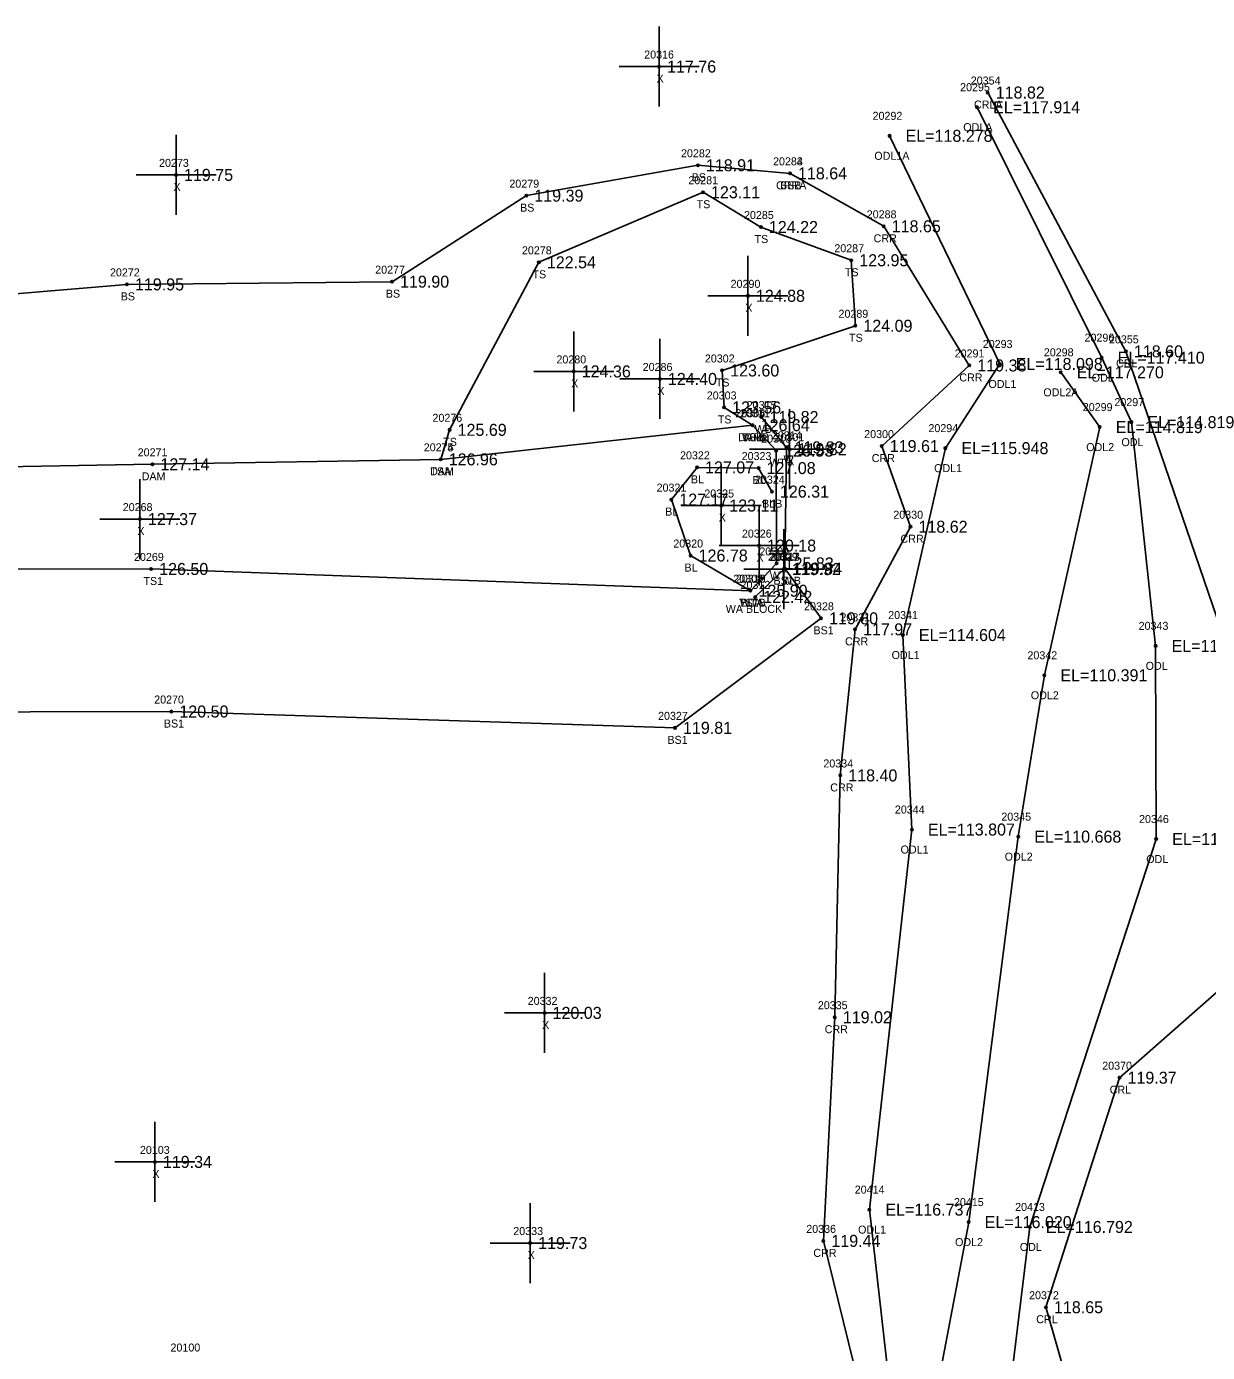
# Model space of a CAD drawing. Extents: x 2375812 to 2377225, y 1024470 to 1025135.
# Drawn here: x 2376402.6 to 2376550.1, y 1024966.8 to 1025132.5 of the extents above; entities that cross this region are included whole.
import ezdxf

# ---------------------------------------------------------------- set-up
doc = ezdxf.new("R2010")
doc.units = 0
for name, color, linetype in [('RD_DTM_BkLn1', 7, 'Continuous'), ('RD_DTM_BkLn2', 7, 'Continuous'), ('RD_DTM_BkLn_txCode', 7, 'Continuous'), ('RD_EX_BldgApp', 7, 'Continuous'), ('RD_EX_Dam', 7, 'Continuous'), ('RD_EX_Dam_txCode', 7, 'Continuous'), ('RD_EX_H2O', 7, 'Continuous'), ('RD_EX_H2O_txCode', 7, 'Continuous'), ('RD_EX_Misc', 7, 'Continuous'), ('RD_EX_Misc_txCode', 7, 'Continuous'), ('RD_EX_TX_Dam_ELEV', 7, 'Continuous'), ('RD_EX_TX_H2O_ELEV', 7, 'Continuous'), ('RD_EX_TX_Misc_ELEV', 7, 'Continuous'), ('RD_SMD_Locator', 7, 'Continuous')]:
    doc.layers.add(name, color=color, linetype=linetype)

msp = doc.modelspace()

# ---------------------------------------------------------------- linework, layer by layer
at = {"layer": 'RD_DTM_BkLn1'}
msp.add_lwpolyline([(2376493.03, 1025062.01), (2376485.55, 1025066.41), (2376483.14, 1025073.4), (2376486.35, 1025077.43), (2376494.04, 1025077.34), (2376495.71, 1025074.4)], dxfattribs=at)
at = {"layer": 'RD_DTM_BkLn2'}
for points in [[(2375847.51, 1025092.15), (2375876.46, 1025088.72), (2375981.63, 1025092.39), (2376090.5, 1025090.54), (2376205.11, 1025096.35), (2376313.64, 1025091.79), (2376415.11, 1025100.3), (2376448.24, 1025100.64), (2376465.02, 1025111.39), (2376486.46, 1025115.19), (2376497.97, 1025114.18)], [(2376454.32, 1025078.43), (2376455.43, 1025082.12), (2376466.58, 1025103.06), (2376487.1, 1025111.82), (2376494.33, 1025107.47), (2376505.63, 1025103.32), (2376506.14, 1025095.13), (2376489.49, 1025089.54), (2376489.73, 1025084.92), (2376493.3, 1025082.7)], [(2375847.93, 1025050.33), (2375875.91, 1025056.72), (2375981.44, 1025060.56), (2376091.98, 1025062.38), (2376205.71, 1025062.75), (2376313.72, 1025064.62), (2376418.13, 1025064.73), (2376493.03, 1025062.01)], [(2375848.17, 1025037.34), (2375876.1, 1025042.73), (2375981.89, 1025042.57), (2376092.59, 1025040.39), (2376206.51, 1025041.77), (2376314.64, 1025046.65), (2376420.66, 1025046.91), (2376483.6, 1025044.87), (2376501.85, 1025058.56), (2376497.33, 1025064.77)]]:
    msp.add_lwpolyline(points, dxfattribs=at)
at = {"layer": 'RD_EX_BldgApp'}
for points in [[(2376493.03, 1025062.01), (2376496.3, 1025065.42), (2376496.24, 1025079.52), (2376493.3, 1025082.7)], [(2376493.62, 1025061.24), (2376497.33, 1025064.77), (2376497.53, 1025079.93), (2376494.4, 1025083.72)]]:
    msp.add_lwpolyline(points, dxfattribs=at)
at = {"layer": 'RD_EX_Dam'}
msp.add_lwpolyline([(2375847.73, 1025068.2), (2375876.5, 1025071.72), (2375981.19, 1025074.08), (2376091.91, 1025074.48), (2376205.24, 1025076.35), (2376314.21, 1025075.97), (2376418.29, 1025077.81), (2376454.32, 1025078.43), (2376493.3, 1025082.7)], dxfattribs=at)
at = {"layer": 'RD_EX_H2O'}
for points in [[(2376522.68, 1025124.28), (2376539.95, 1025091.93), (2376552.99, 1025053.79), (2376555.76, 1025047.24), (2376554.71, 1025040.88), (2376557.55, 1025026.68), (2376555.84, 1025015.85), (2376539.15, 1025001.14), (2376529.96, 1024972.45), (2376538.09, 1024944), (2376543.21, 1024910.85), (2376536.76, 1024892.22), (2376537.46, 1024874.15), (2376528.94, 1024859.35), (2376567.86, 1024843.78), (2376572.98, 1024831.38), (2376577.78, 1024803.44), (2376559.73, 1024782.76)], [(2376521.35, 1025122.45), (2376536.92, 1025091.14), (2376540.63, 1025083.08), (2376543.66, 1025055.12), (2376543.73, 1025030.97), (2376527.94, 1024982.48), (2376525.52, 1024962.71), (2376529, 1024940.86), (2376531.15, 1024912.48), (2376521.82, 1024868), (2376529.09, 1024848.8), (2376562.19, 1024842.5), (2376569.47, 1024830.15), (2376574.05, 1024803.85), (2376558.51, 1024784.52), (2376559.64, 1024766), (2376613.77, 1024719.65), (2376596.93, 1024694.68), (2376526.36, 1024664.12), (2376525.63, 1024655.55), (2376574.03, 1024595.3), (2376579.09, 1024545.56), (2376560.1, 1024512.81), (2376580.22, 1024476.29)], [(2376510.41, 1025118.87), (2376524.18, 1025090.35), (2376517.39, 1025079.83), (2376512.07, 1025056.47), (2376513.2, 1025032.16), (2376507.89, 1024984.65), (2376510.96, 1024957.77), (2376506.15, 1024940.79), (2376503.27, 1024912.21), (2376508.8, 1024872.61), (2376520.24, 1024833.34), (2376559.55, 1024828.46), (2376560.55, 1024802.93), (2376553.87, 1024788.72), (2376548.34, 1024764.64), (2376601.21, 1024719.97), (2376590.62, 1024704.71), (2376516.74, 1024677.65), (2376510.14, 1024650.4), (2376567.6, 1024571.64), (2376569.87, 1024553.24), (2376548.12, 1024513.5), (2376565.22, 1024475.98)], [(2376497.97, 1025114.18), (2376509.68, 1025107.56), (2376520.38, 1025090.17), (2376509.44, 1025080.09), (2376513.03, 1025070.01), (2376506.1, 1025057.18), (2376504.25, 1025038.92), (2376503.57, 1025008.7), (2376502.14, 1024980.74), (2376507.14, 1024960.43), (2376497.53, 1024949.18), (2376497, 1024946.35), (2376491.09, 1024911.59), (2376491.85, 1024896.06), (2376492.09, 1024868.56), (2376505.72, 1024835.56), (2376529.83, 1024824.06), (2376555.53, 1024827.27), (2376554.79, 1024808.22), (2376551.26, 1024790.28)], [(2376531.81, 1025089.31), (2376536.68, 1025082.46), (2376529.76, 1025051.44), (2376526.5, 1025031.27), (2376520.3, 1024983.09), (2376515.68, 1024958.74), (2376517.02, 1024940.85), (2376517.68, 1024912.41), (2376515.57, 1024873.2), (2376528.33, 1024834.7)]]:
    msp.add_lwpolyline(points, dxfattribs=at)
at = {"layer": 'RD_EX_Misc'}
for p, q in [((2376481.61, 1025122.53), (2376481.61, 1025132.53)), ((2376476.61, 1025127.53), (2376486.61, 1025127.53)), ((2376421.24, 1025108.99), (2376421.24, 1025118.99)), ((2376416.24, 1025113.99), (2376426.24, 1025113.99)), ((2376492.71, 1025093.87), (2376492.71, 1025103.87)), ((2376487.71, 1025098.87), (2376497.71, 1025098.87)), ((2376470.94, 1025084.42), (2376470.94, 1025094.42)), ((2376481.71, 1025083.48), (2376481.71, 1025093.48)), ((2376465.94, 1025089.42), (2376475.94, 1025089.42)), ((2376476.71, 1025088.48), (2376486.71, 1025088.48)), ((2376497.92, 1025074.7), (2376497.92, 1025084.7)), ((2376492.92, 1025079.7), (2376502.92, 1025079.7)), ((2376489.38, 1025067.66), (2376489.38, 1025077.66)), ((2376416.73, 1025065.96), (2376416.73, 1025075.96)), ((2376484.38, 1025072.66), (2376494.38, 1025072.66)), ((2376494.1, 1025062.65), (2376494.1, 1025072.65)), ((2376411.73, 1025070.96), (2376421.73, 1025070.96)), ((2376497.2, 1025059.71), (2376497.2, 1025069.71)), ((2376489.1, 1025067.65), (2376499.1, 1025067.65)), ((2376492.2, 1025064.71), (2376502.2, 1025064.71)), ((2376467.3, 1025004.24), (2376467.3, 1025014.24)), ((2376462.3, 1025009.24), (2376472.3, 1025009.24)), ((2376418.6, 1024985.61), (2376418.6, 1024995.61)), ((2376413.6, 1024990.61), (2376423.6, 1024990.61)), ((2376465.5, 1024975.47), (2376465.5, 1024985.47)), ((2376460.5, 1024980.47), (2376470.5, 1024980.47))]:
    msp.add_line(p, q, dxfattribs=at)
at = {"layer": 'RD_SMD_Locator'}
for centre in [(2376481.61, 1025127.53), (2376522.68, 1025124.28), (2376521.35, 1025122.45), (2376510.41, 1025118.87), (2376421.24, 1025113.99), (2376486.46, 1025115.19), (2376497.97, 1025114.18), (2376497.97, 1025114.18), (2376465.02, 1025111.39), (2376487.1, 1025111.82), (2376494.33, 1025107.47), (2376509.68, 1025107.56), (2376466.58, 1025103.06), (2376505.63, 1025103.32), (2376448.24, 1025100.64), (2376415.11, 1025100.3), (2376492.71, 1025098.87), (2376506.14, 1025095.13), (2376536.92, 1025091.14), (2376539.95, 1025091.93), (2376470.94, 1025089.42), (2376489.49, 1025089.54), (2376520.38, 1025090.17), (2376524.18, 1025090.35), (2376531.81, 1025089.31), (2376481.71, 1025088.48), (2376489.73, 1025084.92), (2376493.3, 1025082.7), (2376493.3, 1025082.7), (2376493.3, 1025082.7), (2376494.4, 1025083.72), (2376536.68, 1025082.46), (2376540.63, 1025083.08), (2376455.43, 1025082.12), (2376496.24, 1025079.52), (2376497.53, 1025079.93), (2376497.92, 1025079.7), (2376509.44, 1025080.09), (2376517.39, 1025079.83), (2376418.29, 1025077.81), (2376454.32, 1025078.43), (2376454.32, 1025078.43), (2376486.35, 1025077.43), (2376494.04, 1025077.34), (2376495.71, 1025074.4), (2376483.14, 1025073.4), (2376489.38, 1025072.66), (2376416.73, 1025070.96), (2376513.03, 1025070.01), (2376494.1, 1025067.65), (2376485.55, 1025066.41), (2376418.13, 1025064.73), (2376496.3, 1025065.42), (2376497.2, 1025064.71), (2376497.33, 1025064.77), (2376497.33, 1025064.77), (2376493.03, 1025062.01), (2376493.03, 1025062.01), (2376493.03, 1025062.01), (2376493.62, 1025061.24), (2376501.85, 1025058.56), (2376506.1, 1025057.18), (2376512.07, 1025056.47), (2376543.66, 1025055.12), (2376529.76, 1025051.44), (2376420.66, 1025046.91), (2376483.6, 1025044.87), (2376504.25, 1025038.92), (2376513.2, 1025032.16), (2376526.5, 1025031.27), (2376543.73, 1025030.97), (2376467.3, 1025009.24), (2376503.57, 1025008.7), (2376539.15, 1025001.14), (2376418.6, 1024990.61), (2376507.89, 1024984.65), (2376520.3, 1024983.09), (2376527.94, 1024982.48), (2376465.5, 1024980.47), (2376502.14, 1024980.74), (2376529.96, 1024972.45)]:
    msp.add_circle(centre, 0.15, dxfattribs=at)

# ---------------------------------------------------------------- texts
at = {"layer": 'RD_DTM_BkLn_txCode'}
for s, p in [('20282', (2376484.35, 1025116.19)), ('20283', (2376495.85, 1025115.18)), ('BS', (2376485.68, 1025113.19)), ('20279', (2376462.9, 1025112.39)), ('20281', (2376485.26, 1025112.82)), ('BSB', (2376496.72, 1025112.18)), ('TS', (2376486.3, 1025109.82)), ('BS', (2376464.24, 1025109.39)), ('20285', (2376492.22, 1025108.47)), ('TS', (2376493.54, 1025105.47)), ('20278', (2376464.47, 1025104.06)), ('20287', (2376503.51, 1025104.32)), ('20277', (2376446.13, 1025101.64)), ('20272', (2376412.99, 1025101.3)), ('TS', (2376465.79, 1025101.06)), ('TS', (2376504.83, 1025101.32)), ('BS', (2376414.33, 1025098.3)), ('BS', (2376447.46, 1025098.64)), ('20289', (2376504.03, 1025096.13)), ('TS', (2376505.35, 1025093.13)), ('20302', (2376487.33, 1025090.54)), ('TS', (2376488.69, 1025087.54)), ('20303', (2376487.57, 1025085.92)), ('20305', (2376491.14, 1025083.7)), ('20276', (2376453.29, 1025083.12)), ('TS', (2376488.94, 1025082.92)), ('TS', (2376454.63, 1025080.12)), ('TSB', (2376492.03, 1025080.7)), ('20275', (2376452.2, 1025079.43)), ('20322', (2376484.23, 1025078.43)), ('20323', (2376491.93, 1025078.34)), ('TSA', (2376453.03, 1025076.43)), ('BL', (2376485.59, 1025075.43)), ('BL', (2376493.29, 1025075.34)), ('20324', (2376493.59, 1025075.4)), ('20321', (2376481.3, 1025074.4)), ('BLB', (2376494.48, 1025072.4)), ('BL', (2376482.38, 1025071.4)), ('20320', (2376483.39, 1025067.41)), ('20269', (2376415.99, 1025065.73)), ('20329', (2376495.21, 1025065.77)), ('BL', (2376484.79, 1025064.41)), ('TS1', (2376417.17, 1025062.73)), ('20318', (2376491.2, 1025063.01)), ('20319', (2376491.2, 1025063.01)), ('BS1B', (2376495.91, 1025062.77)), ('TS1B', (2376491.6, 1025060.01)), ('BLA', (2376491.79, 1025060.01)), ('20328', (2376499.73, 1025059.56)), ('BS1', (2376500.9, 1025056.56)), ('20270', (2376418.51, 1025047.91)), ('20327', (2376481.48, 1025045.87)), ('BS1', (2376419.72, 1025044.91)), ('BS1', (2376482.65, 1025042.87))]:
    msp.add_text(s, height=1, dxfattribs=at).set_placement(p)
at = {"layer": 'RD_EX_Dam_txCode'}
for s, p in [('20304', (2376491.14, 1025083.7)), ('DAMB', (2376491.49, 1025080.7)), ('20271', (2376416.45, 1025078.81)), ('20274', (2376452.2, 1025079.43)), ('DAM', (2376416.95, 1025075.81)), ('DAM', (2376452.99, 1025076.43))]:
    msp.add_text(s, height=1, dxfattribs=at).set_placement(p)
at = {"layer": 'RD_EX_H2O_txCode'}
for s, p in [('20354', (2376520.56, 1025125.28)), ('20295', (2376519.23, 1025124.45)), ('CRLA', (2376520.96, 1025122.28)), ('20292', (2376508.29, 1025120.87)), ('ODLA', (2376519.62, 1025119.45)), ('20284', (2376495.85, 1025115.18)), ('ODL1A', (2376508.51, 1025115.87)), ('CRRA', (2376496.23, 1025112.18)), ('20288', (2376507.56, 1025108.56)), ('CRR', (2376508.42, 1025105.56)), ('20296', (2376534.78, 1025093.14)), ('20293', (2376522.06, 1025092.35)), ('20355', (2376537.83, 1025092.93)), ('20291', (2376518.55, 1025091.17)), ('20298', (2376529.69, 1025091.31)), ('CRL', (2376538.72, 1025089.93)), ('CRR', (2376519.13, 1025088.17)), ('ODL', (2376535.68, 1025088.14)), ('ODL1', (2376522.77, 1025087.35)), ('ODL2A', (2376529.63, 1025086.31)), ('20297', (2376538.51, 1025085.08)), ('20299', (2376534.56, 1025084.46)), ('20294', (2376515.27, 1025081.83)), ('20300', (2376507.24, 1025081.09)), ('ODL', (2376539.39, 1025080.08)), ('ODL2', (2376534.99, 1025079.46)), ('CRR', (2376508.18, 1025078.09)), ('ODL1', (2376515.98, 1025076.83)), ('20330', (2376510.88, 1025071.01)), ('CRR', (2376511.78, 1025068.01)), ('20341', (2376510.24, 1025058.47)), ('20331', (2376504.27, 1025058.18)), ('20343', (2376541.54, 1025057.12)), ('CRR', (2376504.85, 1025055.18)), ('ODL1', (2376510.67, 1025053.47)), ('20342', (2376527.64, 1025053.44)), ('ODL', (2376542.42, 1025052.12)), ('ODL2', (2376528.07, 1025048.44)), ('20334', (2376502.14, 1025039.92)), ('CRR', (2376503, 1025036.92)), ('20344', (2376511.08, 1025034.16)), ('20345', (2376524.38, 1025033.27)), ('20346', (2376541.59, 1025032.97)), ('ODL1', (2376511.79, 1025029.16)), ('ODL2', (2376524.8, 1025028.27)), ('ODL', (2376542.49, 1025027.97)), ('20335', (2376501.45, 1025009.7)), ('CRR', (2376502.31, 1025006.7)), ('20370', (2376536.99, 1025002.14)), ('CRL', (2376537.92, 1024999.14)), ('20414', (2376506.06, 1024986.65)), ('20415', (2376518.46, 1024985.09)), ('20413', (2376526.1, 1024984.48)), ('20336', (2376500, 1024981.74)), ('ODL1', (2376506.48, 1024981.65)), ('ODL2', (2376518.6, 1024980.09)), ('ODL', (2376526.69, 1024979.48)), ('CRR', (2376500.89, 1024978.74)), ('20372', (2376527.85, 1024973.45)), ('CRL', (2376528.74, 1024970.45)), ('20100', (2376420.55, 1024966.91))]:
    msp.add_text(s, height=1, dxfattribs=at).set_placement(p)
at = {"layer": 'RD_EX_Misc_txCode'}
for s, p in [('20316', (2376479.75, 1025128.53)), ('X', (2376481.3, 1025125.53)), ('20273', (2376419.12, 1025114.99)), ('X', (2376420.93, 1025111.99)), ('20290', (2376490.55, 1025099.87)), ('X', (2376492.39, 1025096.87)), ('20280', (2376468.78, 1025090.42)), ('20286', (2376479.56, 1025089.48)), ('X', (2376470.62, 1025087.42)), ('X', (2376481.39, 1025086.48)), ('20311', (2376491.74, 1025083.7)), ('20315', (2376492.56, 1025084.72)), ('WB', (2376493.55, 1025081.72)), ('WTB', (2376491.96, 1025080.7)), ('20310', (2376494.37, 1025080.52)), ('20314', (2376495.7, 1025080.93)), ('20301', (2376496.04, 1025080.7)), ('WT', (2376495.38, 1025077.52)), ('W', (2376497.16, 1025077.93)), ('X', (2376497.6, 1025077.7)), ('20325', (2376487.26, 1025073.66)), ('20268', (2376414.58, 1025071.96)), ('X', (2376489.07, 1025070.66)), ('X', (2376416.41, 1025068.96)), ('20326', (2376491.96, 1025068.65)), ('X', (2376493.79, 1025065.65)), ('20309', (2376494.14, 1025066.42)), ('20317', (2376495.37, 1025065.71)), ('20313', (2376495.49, 1025065.77)), ('WT', (2376495.44, 1025063.42)), ('20308', (2376490.88, 1025063.01)), ('20312', (2376491.79, 1025062.24)), ('X', (2376496.89, 1025062.71)), ('W', (2376496.96, 1025062.77)), ('WTA', (2376491.69, 1025060.01)), ('WA BLOCK', (2376489.94, 1025059.24)), ('20332', (2376465.19, 1025010.24)), ('X', (2376466.99, 1025007.24)), ('20103', (2376416.73, 1024991.61)), ('X', (2376418.29, 1024988.61)), ('20333', (2376463.39, 1024981.47)), ('X', (2376465.19, 1024978.47))]:
    msp.add_text(s, height=1, dxfattribs=at).set_placement(p)
at = {"layer": 'RD_EX_TX_Dam_ELEV'}
for s, p in [('126.64', (2376494.3, 1025081.95)), ('127.14', (2376419.29, 1025077.06)), ('126.96', (2376455.32, 1025077.68))]:
    msp.add_text(s, height=1.5, dxfattribs=at).set_placement(p)
at = {"layer": 'RD_EX_TX_H2O_ELEV'}
for s, p in [('118.82', (2376523.68, 1025123.53)), ('EL=117.914', (2376523.35, 1025121.7)), ('EL=118.278', (2376512.41, 1025118.12)), ('118.64', (2376498.97, 1025113.43)), ('118.65', (2376510.68, 1025106.81)), ('118.60', (2376540.95, 1025091.18)), ('119.38', (2376521.38, 1025089.42)), ('EL=118.098', (2376526.18, 1025089.6)), ('EL=117.410', (2376538.92, 1025090.39)), ('EL=117.270', (2376533.81, 1025088.56)), ('EL=114.819', (2376538.68, 1025081.71)), ('EL=114.819', (2376542.63, 1025082.33)), ('119.61', (2376510.44, 1025079.34)), ('EL=115.948', (2376519.39, 1025079.08)), ('118.62', (2376514.03, 1025069.26)), ('117.97', (2376507.1, 1025056.43)), ('EL=114.604', (2376514.07, 1025055.72)), ('EL=110.147', (2376545.66, 1025054.37)), ('EL=110.391', (2376531.76, 1025050.69)), ('118.40', (2376505.25, 1025038.17)), ('EL=113.807', (2376515.2, 1025031.41)), ('EL=110.668', (2376528.5, 1025030.52)), ('EL=110.554', (2376545.73, 1025030.22)), ('119.02', (2376504.57, 1025007.95)), ('119.37', (2376540.15, 1025000.39)), ('EL=116.737', (2376509.89, 1024983.9)), ('EL=116.020', (2376522.3, 1024982.34)), ('EL=116.792', (2376529.94, 1024981.73)), ('119.44', (2376503.14, 1024979.99)), ('118.65', (2376530.96, 1024971.7))]:
    msp.add_text(s, height=1.5, dxfattribs=at).set_placement(p)
at = {"layer": 'RD_EX_TX_Misc_ELEV'}
for s, p in [('117.76', (2376482.61, 1025126.78)), ('118.91', (2376487.46, 1025114.44)), ('119.75', (2376422.24, 1025113.24)), ('118.64', (2376498.97, 1025113.43)), ('123.11', (2376488.1, 1025111.07)), ('119.39', (2376466.02, 1025110.64)), ('124.22', (2376495.33, 1025106.72)), ('123.95', (2376506.63, 1025102.57)), ('122.54', (2376467.58, 1025102.31)), ('119.95', (2376416.11, 1025099.55)), ('119.90', (2376449.24, 1025099.89)), ('124.88', (2376493.71, 1025098.12)), ('124.09', (2376507.14, 1025094.38)), ('124.36', (2376471.94, 1025088.67)), ('124.40', (2376482.71, 1025087.73)), ('123.60', (2376490.49, 1025088.79)), ('123.56', (2376490.73, 1025084.17)), ('119.82', (2376495.4, 1025082.97)), ('125.69', (2376456.43, 1025081.37)), ('126.64', (2376494.3, 1025081.95)), ('126.64', (2376494.3, 1025081.95)), ('126.53', (2376497.24, 1025078.77)), ('119.83', (2376498.53, 1025079.18)), ('119.82', (2376498.92, 1025078.95)), ('126.96', (2376455.32, 1025077.68)), ('127.07', (2376487.35, 1025076.68)), ('127.08', (2376495.04, 1025076.59)), ('126.31', (2376496.71, 1025073.65)), ('127.17', (2376484.14, 1025072.65)), ('123.11', (2376490.38, 1025071.91)), ('127.37', (2376417.73, 1025070.21)), ('120.18', (2376495.1, 1025066.9)), ('126.78', (2376486.55, 1025065.66)), ('125.83', (2376497.3, 1025064.67)), ('126.50', (2376419.13, 1025063.98)), ('119.92', (2376498.2, 1025063.96)), ('119.84', (2376498.33, 1025064.02)), ('119.84', (2376498.33, 1025064.02)), ('125.90', (2376494.03, 1025061.26)), ('125.90', (2376494.03, 1025061.26)), ('125.90', (2376494.03, 1025061.26)), ('122.42', (2376494.62, 1025060.49)), ('119.80', (2376502.85, 1025057.81)), ('120.50', (2376421.66, 1025046.16)), ('119.81', (2376484.6, 1025044.12)), ('120.03', (2376468.3, 1025008.49)), ('119.34', (2376419.6, 1024989.86)), ('119.73', (2376466.5, 1024979.72))]:
    msp.add_text(s, height=1.5, dxfattribs=at).set_placement(p)

doc.saveas('drawing.dxf')
